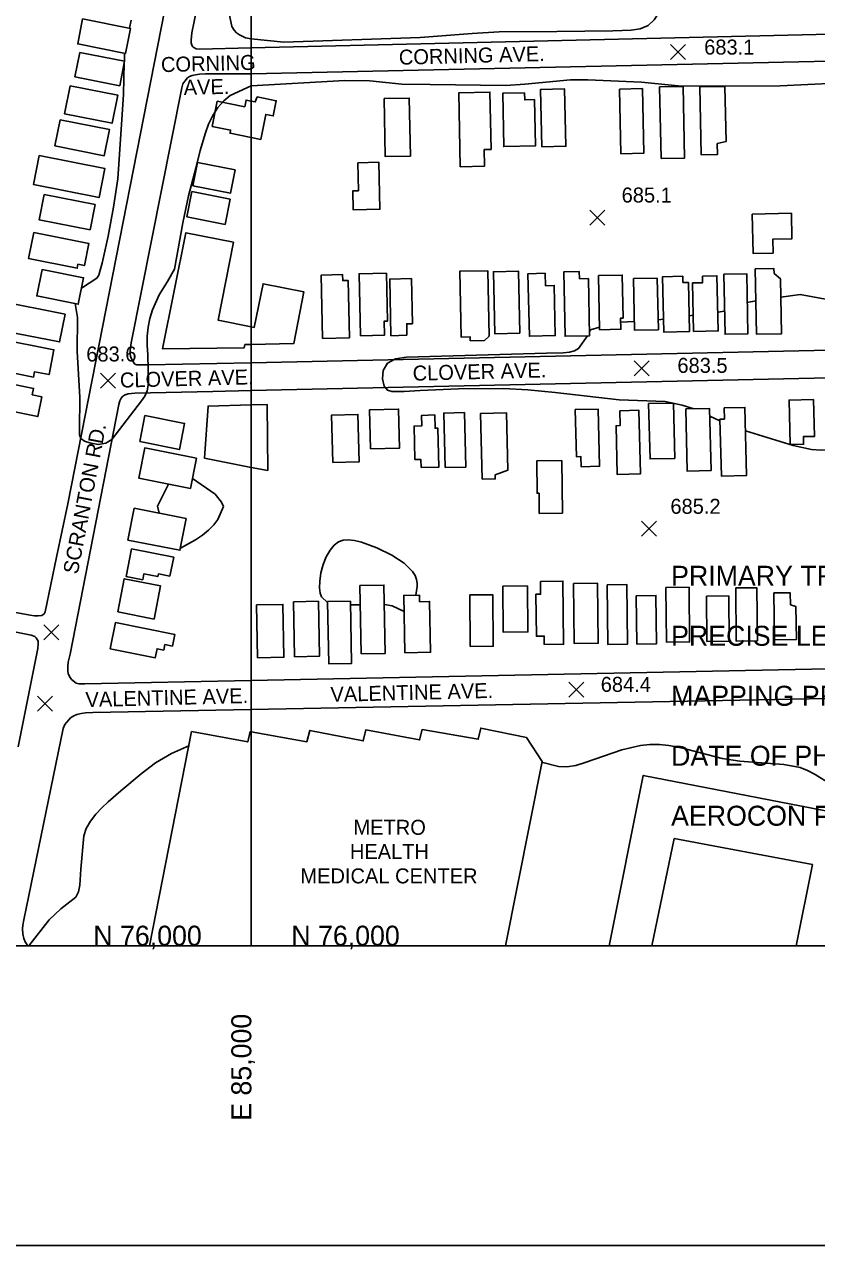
# Model space of a CAD drawing. Extents: x 79600 to 91800, y 75600 to 84400.
# Drawn here: x 84773 to 85566, y 75700 to 76922 of the extents above; entities that cross this region are included whole.
import ezdxf

# ---------------------------------------------------------------- set-up
doc = ezdxf.new("R2010")
doc.units = 0
for name, color, linetype in [('080-085$0$BLDG', 7, 'Continuous'), ('080-085$0$GRID', 7, 'Continuous'), ('080-085$0$INTER', 7, 'Continuous'), ('080-085$0$ROAD', 7, 'Continuous'), ('080-085$0$ROAD-NAME', 7, 'Continuous'), ('080-085$0$SPOTMARK', 7, 'Continuous'), ('080-085$0$SPOTS', 7, 'Continuous'), ('080-085$0$TI_BORDER', 7, 'Continuous'), ('080-085$0$TI_TITLE', 7, 'Continuous'), ('080-090$0$BLDG', 7, 'Continuous'), ('080-090$0$GRID', 7, 'Continuous'), ('080-090$0$INTER', 7, 'Continuous'), ('080-090$0$ROAD', 7, 'Continuous'), ('080-090$0$ROAD-NAME', 7, 'Continuous'), ('080-090$0$SPOTMARK', 7, 'Continuous'), ('080-090$0$SPOTS', 7, 'Continuous'), ('080-090$0$TI_BORDER', 7, 'Continuous')]:
    doc.layers.add(name, color=color, linetype=linetype)

# ---------------------------------------------------------------- blocks, each defined once
blk = doc.blocks.new('080-090$0$SPOTS')
at = {"layer": '080-090$0$SPOTMARK'}
for p, q in [((-0.5, -0.5), (0.5, 0.5)), ((-0.5, 0.5), (0.5, -0.5))]:
    blk.add_line(p, q, dxfattribs=at)
blk = doc.blocks.new('080-085$0$SPOTS')
at = {"layer": '080-085$0$SPOTMARK'}
for p, q in [((-0.5, -0.5), (0.5, 0.5)), ((-0.5, 0.5), (0.5, -0.5))]:
    blk.add_line(p, q, dxfattribs=at)

msp = doc.modelspace()

# ---------------------------------------------------------------- linework, layer by layer
at = {"layer": '080-085$0$BLDG'}
for points in [[(84831.2, 76927.1), (84826.3, 76902.1), (84874, 76892.6), (84879, 76917.6)], [(84828.3, 76893.6), (84823.5, 76869.2), (84868.3, 76860.3), (84873.2, 76884.7)], [(84818.7, 76860.2), (84813.2, 76832.1), (84860.7, 76822.7), (84866.3, 76850.8)], [(84808.7, 76826.2), (84803.5, 76800), (84852.8, 76790.2), (84858, 76816.5)], [(84787.9, 76790.3), (84782.2, 76761.4), (84847.7, 76748.4), (84853.5, 76777.3)], [(84946.2, 76783.6), (84983.8, 76776), (84979.1, 76752.6), (84941.5, 76760.2)], [(84792.6, 76751.5), (84787.6, 76726.2), (84838.7, 76716.1), (84843.7, 76741.4)], [(84940.5, 76754.3), (84978.8, 76746.6), (84973.8, 76721.5), (84935.5, 76729.2)], [(84782.4, 76713.3), (84777.2, 76687.3), (84825.8, 76677.7), (84826.6, 76681.6), (84833.1, 76680.3), (84837.5, 76702.3)], [(84790.6, 76676.5), (84785.3, 76649.9), (84826.9, 76641.7), (84832.2, 76668.2)], [(84746.5, 76645), (84743.4, 76629.5), (84757.3, 76626.7), (84754.9, 76614.5), (84808.2, 76603.9), (84813.7, 76631.7)], [(84745.2, 76607.4), (84741.5, 76588.8), (84734.9, 76590.2), (84732.6, 76578.6), (84782.1, 76568.8), (84783.1, 76574.1), (84797.6, 76571.3), (84802.5, 76596.1)], [(84780.9, 76550.9), (84782.2, 76557.5), (84743, 76565.4), (84740.2, 76551.7), (84729.2, 76553.9), (84726.6, 76541.3), (84786.4, 76529.3), (84790.3, 76549)], [(84888.4, 76504.2), (84893.6, 76530.2), (84933.3, 76522.4), (84928.1, 76496.3)], [(84945.1, 76487.6), (84893.4, 76497.9), (84887.4, 76467.7), (84939.1, 76457.4)], [(84934.9, 76427.2), (84882.9, 76437.5), (84876.6, 76405.8), (84928.6, 76395.5)], [(84918.6, 76369.6), (84907, 76371.9), (84906.4, 76369.3), (84892.6, 76372.1), (84891.4, 76366.1), (84874.7, 76369.4), (84880.2, 76396.9), (84922.4, 76388.5)], [(84866.3, 76333.9), (84872.8, 76367), (84909.3, 76359.8), (84902.7, 76326.7)], [(84921.1, 76299.7), (84913.5, 76301.2), (84912.4, 76295.7), (84905.7, 76297.1), (84903.9, 76288), (84858.8, 76297), (84864, 76323.2), (84923.4, 76311.4)]]:
    msp.add_lwpolyline(points, close=True, dxfattribs=at)
for points in [[(85000, 76808.4), (84978.7, 76812.7), (84979.3, 76815.8), (84960.9, 76819.5), (84965.9, 76844.7)], [(84965.9, 76844.7), (84993.5, 76839.2), (84994.8, 76845.9), (85000, 76844.8)], [(85000, 76601.4), (84993.6, 76601.3), (84992.9, 76598.1), (84911.3, 76596.9), (84934.6, 76713.2), (84982.3, 76703.6)], [(84982.3, 76703.6), (84966.7, 76625.8), (85000, 76619.1)], [(85000, 76541), (84956.8, 76539.8), (84953, 76487.8), (85000, 76478.5)], [(85000, 76213.9), (84999, 76214.1), (84996.4, 76203.8), (84940.3, 76214.2), (84898.2, 76000)]]:
    msp.add_lwpolyline(points, dxfattribs=at)
at = {"layer": '080-085$0$GRID'}
for p, q in [((85000, 80000), (85000, 76000)), ((85000, 76000), (80000, 76000))]:
    msp.add_line(p, q, dxfattribs=at)
at = {"layer": '080-085$0$INTER'}
for p, q in [((84879.7, 76925.7), (84878, 76917.8)), ((84873.1, 76892.8), (84873, 76884.8))]:
    msp.add_line(p, q, dxfattribs=at)
for points in [[(85000, 76907), (84994.2, 76908.2), (84988.3, 76911), (84985.3, 76913.2), (84982.7, 76915.9), (84980.6, 76919.6), (84977.9, 76932.5), (84974.5, 76968.3), (84973.5, 76986), (84974.5, 77004.8), (84977.5, 77023.9), (84981.9, 77041.5), (84990.1, 77066.8), (85000, 77090.7)], [(84872.9, 76883.5), (84872, 76851.5), (84867.9, 76786.7), (84866.3, 76767.2), (84862.1, 76738.6), (84856.7, 76709.8), (84850.7, 76682.6), (84848.9, 76675.8), (84847.3, 76670.9), (84845.4, 76667.6), (84830.1, 76657.7)], [(84823.9, 76642.3), (84826.2, 76628.4), (84825.9, 76594.5), (84828.5, 76548.8), (84828.1, 76516), (84828.2, 76511.1), (84829.5, 76507.5), (84833, 76504.8), (84839.3, 76502.6), (84847, 76501.5), (84854.4, 76502.6), (84860.3, 76506.5), (84890.1, 76545), (84893.4, 76549.6), (84895.8, 76555.1), (84897, 76562.8), (84896.5, 76591.2), (84895.9, 76600.6), (84895.9, 76609.7), (84896.8, 76618.8), (84898.6, 76627.5), (84901.2, 76635.9), (84907.9, 76651.1), (84916.1, 76664.3), (84923.3, 76676.9), (84931.5, 76723), (84937.3, 76750.2), (84944.4, 76777.7), (84948.9, 76795.3), (84954.1, 76813.1), (84957.3, 76821.9), (84961.4, 76830.4), (84966.5, 76838.3), (84972.5, 76845.1), (84979, 76850.6), (85000, 76860.2)], [(84917.2, 76461.8), (84906.2, 76439.8), (84907.7, 76432.6)], [(84972.2, 76439.3), (84970.1, 76443.7), (84963.8, 76451.6), (84941.1, 76467.4)], [(84929, 76397.6), (84944.2, 76406), (84951, 76410.5), (84957.2, 76415.6), (84962.4, 76421), (84966.4, 76426.2), (84972.2, 76439.3)], [(84938.3, 76200.1), (84920.1, 76192.1), (84904.1, 76182.8), (84889.7, 76171.9), (84869.3, 76155), (84856.7, 76144), (84850.5, 76138), (84844.5, 76131.5), (84839.1, 76124.5), (84834.9, 76117.2), (84832.3, 76109.9), (84829.3, 76076.7), (84828.3, 76060.4), (84827.1, 76053.9), (84824.6, 76048.6), (84809.5, 76037), (84797.9, 76025.7), (84777.3, 76000)]]:
    msp.add_lwpolyline(points, dxfattribs=at)
at = {"layer": '080-085$0$ROAD'}
for p, q in [((84998.9, 76872.3), (85000, 76872.3)), ((84961.6, 76554.4), (85000, 76555.2))]:
    msp.add_line(p, q, dxfattribs=at)
for points in [[(85000, 76898.1), (84948.3, 76896.9), (84944.7, 76897.2), (84942.4, 76898.4), (84941.4, 76899.2), (84940.5, 76900.9), (84939.8, 76903), (84939.9, 76905.9), (84940, 76909.5), (84940.4, 76913), (84994.1, 77174.3), (84995.6, 77179.1), (84997.7, 77182), (85000, 77184.1)], [(84689.6, 77082.2), (84919.5, 77085.7), (84922.4, 77085.8), (84925.3, 77085.5), (84928.1, 77085.1), (84930, 77084.1), (84931.5, 77083.2), (84934.4, 77080.5), (84936, 77078.5), (84937.6, 77075.6), (84938.3, 77072.8), (84938.5, 77068.1), (84938.3, 77064.6), (84937.5, 77059.2), (84816.4, 76442.1), (84805.1, 76388.5), (84793.6, 76333.9), (84792.6, 76331.9), (84790.3, 76330.3), (84786.7, 76330), (84783.1, 76330), (84778.8, 76330.6), (84673.2, 76350.1)], [(85000, 76583.2), (84896.8, 76581), (84891, 76580.9), (84885.6, 76581.2), (84884.5, 76581.5), (84883.2, 76582.2), (84882.1, 76583.6), (84879.7, 76587.6), (84879, 76589.6), (84878.7, 76592.1), (84878.7, 76595.7), (84879.9, 76603), (84930.4, 76858.1), (84931.4, 76862), (84933.4, 76864.9), (84936.1, 76868), (84938.3, 76869.4), (84940.8, 76870.6), (84944.2, 76871.2), (84948.3, 76871.8), (84954.3, 76872), (84998.9, 76872.3)], [(85000, 76265.2), (84833.3, 76261.8), (84827.5, 76261.8), (84824.9, 76262.6), (84820.2, 76266.2), (84818.6, 76268.4), (84816.8, 76271.8), (84816.3, 76275.1), (84816.3, 76279.4), (84816.7, 76283.7), (84818.7, 76291.5), (84867.4, 76541.2), (84868.5, 76545), (84869.7, 76547.6), (84871.6, 76549.8), (84873.9, 76551), (84876.9, 76552.1), (84880, 76552.3), (84883.5, 76552.7), (84961.6, 76554.4)], [(84641.7, 76338.4), (84779.6, 76310.5), (84783.3, 76309.4), (84784.7, 76308.1), (84786.6, 76304.5), (84786.8, 76301.8), (84786.5, 76297.4), (84766.6, 76199)], [(84776.2, 76000), (84775.3, 76001.4), (84774.2, 76003.2), (84772.5, 76007.2), (84771.4, 76011.8), (84771.2, 76016.7), (84771.3, 76020.6), (84772.3, 76025.8), (84811.6, 76217.1), (84813.4, 76221.1), (84815.1, 76223.4), (84817.4, 76225.9), (84819.2, 76227.8), (84822.3, 76229.8), (84825.3, 76231.2), (84829.7, 76232.2), (84834, 76232.9), (84841.6, 76233.1), (85000, 76236.2)]]:
    msp.add_lwpolyline(points, dxfattribs=at)
at = {"layer": '080-085$0$TI_BORDER'}
msp.add_lwpolyline([(79700, 80300), (86700, 80300), (86700, 75700), (79700, 75700)], close=True, dxfattribs=at)
at = {"layer": '080-090$0$BLDG'}
msp.add_line((85000, 76478.5), (85016.5, 76475.3), dxfattribs=at)
for points in [[(85000, 76844.8), (85003.9, 76844.1), (85005.9, 76849.1), (85025, 76845.2), (85022, 76830), (85014.5, 76831.5), (85009.5, 76806.5), (85000, 76808.4)], [(85000, 76619.1), (85003, 76618.5), (85011.7, 76662.2), (85052.7, 76653.9), (85042.4, 76602.3), (85000, 76601.4)], [(85016.5, 76475.3), (85015.8, 76541.5), (85000, 76541)], [(85254.2, 76000), (85291, 76184.4), (85275.3, 76208.2), (85229.6, 76217.6), (85227.1, 76206.5), (85170.9, 76216.2), (85168.4, 76205.8), (85114.5, 76215.9), (85112, 76204.9), (85058.7, 76215.3), (85055.4, 76204), (85000, 76213.9)], [(85358.1, 76000), (85392.2, 76170.4), (85612.5, 76127.6), (85587.5, 76000)], [(85400.8, 76000), (85423.2, 76107.1), (85561.4, 76081.1), (85545, 76000)]]:
    msp.add_lwpolyline(points, dxfattribs=at)
for points in [[(85240, 76796.5), (85233, 76796.4), (85233.4, 76779.8), (85209.1, 76779.2), (85207.5, 76853.1), (85238.8, 76853.8)], [(85273.3, 76853.1), (85273.5, 76846.1), (85283.3, 76846.3), (85284.2, 76800.1), (85252.6, 76799.4), (85251.5, 76852.7)], [(85290.6, 76799.2), (85314.8, 76799.7), (85313.5, 76857), (85289.4, 76856.5)], [(85368.4, 76856.9), (85369.7, 76792.2), (85392.6, 76792.7), (85391.3, 76857.4)], [(85409.9, 76787.3), (85433.4, 76787.8), (85431.9, 76859.5), (85408.4, 76859)], [(85466.2, 76802.5), (85466.4, 76791.3), (85450.1, 76791), (85448.7, 76859.1), (85473.9, 76859.6), (85475, 76804.3)], [(85132.8, 76847.3), (85134, 76789.3), (85159.2, 76789.8), (85158, 76847.9)], [(85106.5, 76783.2), (85107.1, 76755.2), (85101.6, 76755.1), (85102, 76736), (85128.6, 76736.6), (85127.6, 76783.7)], [(85522.2, 76692.9), (85521.9, 76706.8), (85540.8, 76707.2), (85540.3, 76732.6), (85501.1, 76731.7), (85502, 76692.5)], [(85071.3, 76607.5), (85070, 76670.8), (85091.3, 76671.3), (85091.4, 76665.3), (85096.9, 76665.4), (85098.2, 76608.1)], [(85109.1, 76610.1), (85107.8, 76672.1), (85135.1, 76672.6), (85136.1, 76624.7), (85132.9, 76624.6), (85133.2, 76610.6)], [(85155.7, 76610.6), (85155.5, 76622.1), (85161.1, 76622.2), (85160.1, 76667.4), (85138.5, 76666.9), (85139.7, 76610.2)], [(85233.4, 76605.5), (85219.1, 76605.2), (85219, 76609), (85209.9, 76608.8), (85208.5, 76674.6), (85236.6, 76675.2), (85238, 76609.8)], [(85268.7, 76612.7), (85243.6, 76612.2), (85242.3, 76674.1), (85267.4, 76674.6)], [(85294.2, 76660.2), (85293.9, 76672.6), (85276.8, 76672.2), (85278.2, 76609.7), (85304.1, 76610.3), (85303, 76660.4)], [(85328.2, 76667.1), (85328.1, 76674.3), (85312.6, 76674), (85314, 76609.6), (85338.4, 76610.1), (85337.2, 76667.3)], [(85347.4, 76670.4), (85348.5, 76616.2), (85369.7, 76616.6), (85369.4, 76627.8), (85372, 76627.8), (85371.1, 76670.9)], [(85406.2, 76667.8), (85382.4, 76667.3), (85383.5, 76615.7), (85407.3, 76616.2)], [(85431.8, 76663.4), (85431.7, 76669.6), (85411.4, 76669.2), (85412.6, 76613.8), (85438.3, 76614.3), (85437.3, 76663.5)], [(85451.3, 76669.9), (85451.5, 76663.2), (85441.4, 76663), (85442.4, 76614.4), (85467.1, 76614.9), (85465.9, 76670.2)], [(85472.7, 76671.8), (85474, 76611.6), (85496.9, 76612.1), (85495.6, 76672.2)], [(85523, 76672.3), (85522.9, 76677.4), (85504.1, 76677), (85505.5, 76611.7), (85530.5, 76612.2), (85529.3, 76667.1)], [(85562.6, 76546.3), (85563.5, 76509.5), (85552.3, 76509.2), (85552.5, 76501.6), (85539.2, 76501.2), (85538.1, 76545.7)], [(85081.5, 76483.3), (85080.3, 76530.7), (85106.7, 76531.4), (85107.9, 76484)], [(85119.4, 76496.9), (85118.4, 76536.1), (85147.3, 76536.8), (85148.2, 76497.6)], [(85193.8, 76478.3), (85192.5, 76532.8), (85213.2, 76533.3), (85214.5, 76478.8)], [(85243.9, 76470.9), (85244, 76467), (85231, 76466.7), (85229.3, 76532.4), (85255.3, 76533.1), (85256.7, 76475.8)], [(85324, 76536.2), (85325.2, 76489.1), (85329.8, 76489.2), (85330, 76479.1), (85348.4, 76479.6), (85347, 76536.7)], [(85368.6, 76535.1), (85369, 76520.2), (85364.9, 76520.1), (85366, 76471.5), (85389.4, 76472.1), (85387.8, 76535.6)], [(85397.5, 76542.2), (85398.9, 76486.9), (85423.7, 76487.5), (85422.3, 76542.8)], [(85434.6, 76536.9), (85436.1, 76474.6), (85460, 76475.2), (85458.4, 76537.5)], [(85473, 76538), (85473.3, 76526.7), (85468.9, 76526.6), (85470.3, 76469.8), (85495.5, 76470.4), (85493.8, 76538.5)], [(85169.8, 76478.3), (85169.6, 76486.4), (85163.7, 76486.3), (85162.9, 76519.7), (85170.6, 76519.9), (85170.3, 76530.5), (85183.6, 76530.9), (85183.9, 76517.6), (85186.7, 76517.6), (85187.7, 76478.8)], [(85288.1, 76432.4), (85287.9, 76452.5), (85285.9, 76452.5), (85285.5, 76485), (85310.6, 76485.3), (85311.2, 76432.7)], [(85108.6, 76360.3), (85110, 76292), (85134, 76292.4), (85132.7, 76360.7)], [(85289.3, 76364.4), (85289.4, 76351.6), (85284.8, 76351.5), (85285.3, 76309.6), (85293, 76309.7), (85293.1, 76301.2), (85312.4, 76301.5), (85311.7, 76364.7)], [(85322.2, 76362.3), (85322.9, 76302.4), (85347.1, 76302.6), (85346.4, 76362.6)], [(85355.9, 76361.1), (85356.6, 76301.4), (85376.3, 76301.6), (85375.6, 76361.3)], [(85168.3, 76344.1), (85168.2, 76350.7), (85152.5, 76350.4), (85153.6, 76293), (85179.3, 76293.5), (85178.3, 76344.3)], [(85218.5, 76350.8), (85219.1, 76299.3), (85242.1, 76299.6), (85241.5, 76351.1)], [(85251.6, 76359.5), (85252.1, 76313.5), (85276.8, 76313.8), (85276.3, 76359.8)], [(85385.2, 76350.1), (85385.8, 76301.7), (85405.3, 76301.9), (85404.8, 76350.3)], [(85414.8, 76358.2), (85415.5, 76303.6), (85438.5, 76303.9), (85437.9, 76358.5)], [(85455.4, 76349.6), (85455.9, 76304.3), (85478.1, 76304.6), (85477.6, 76349.9)], [(85484.6, 76357.9), (85485.2, 76304.6), (85506.3, 76304.8), (85505.7, 76358.1)], [(85539.3, 76341), (85539.1, 76353), (85522.8, 76352.8), (85523.3, 76306), (85545.3, 76306.2), (85544.9, 76339.2)], [(85005.3, 76340.9), (85006.3, 76288.1), (85032.7, 76288.6), (85031.7, 76341.4)], [(85042.2, 76344.1), (85043.3, 76289), (85068.1, 76289.5), (85067.1, 76344.5)], [(85076.3, 76344.2), (85077.5, 76282), (85100.3, 76282.4), (85099.1, 76344.6)]]:
    msp.add_lwpolyline(points, close=True, dxfattribs=at)
at = {"layer": '080-090$0$GRID'}
for p in [(85000, 80000), (90000, 76000)]:
    msp.add_line(p, (85000, 76000), dxfattribs=at)
at = {"layer": '080-090$0$INTER'}
for p, q in [((85496.2, 76643.4), (85504.8, 76645.1)), ((85438, 76630.1), (85442.1, 76630.8)), ((85466.7, 76633.7), (85473.5, 76634.7)), ((85369.5, 76623.8), (85383.3, 76624.4)), ((85407.1, 76626.2), (85412.3, 76626.6)), ((85468.9, 76525.1), (85458.6, 76529.7)), ((85099.1, 76340.9), (85109, 76340.8))]:
    msp.add_line(p, q, dxfattribs=at)
for points in [[(85000, 76907), (85032.4, 76903.9), (85169.1, 76908.6), (85221.1, 76912.5), (85248.1, 76914.1), (85305.8, 76914.4), (85361.8, 76915.2), (85370.9, 76915.4), (85380.2, 76915.8), (85389.2, 76917.2), (85397, 76920.5), (85403.2, 76926.1), (85420.1, 76952.6)], [(85651.5, 76862.4), (85627.5, 76861.5), (85584.6, 76862.7), (85529.1, 76860.2), (85453.8, 76859.8), (85427.1, 76860.3), (85390.3, 76863.7), (85336.8, 76866.2), (85319.2, 76866.3), (85273.6, 76861.7), (85254.6, 76860.5), (85179.1, 76861.4), (85150.5, 76861.7), (85118.6, 76865.3), (85093.7, 76865.5), (85000, 76860.2)], [(85529.7, 76648.7), (85549.1, 76651.3), (85574.6, 76646.7)], [(85338.3, 76614.1), (85339.3, 76615.9), (85348.5, 76618.8)], [(85442.8, 76537.1), (85431.1, 76540.6), (85414.1, 76544.3), (85367.9, 76546.1), (85304.1, 76553.5), (85276.5, 76556.1), (85252.3, 76557.3), (85207.3, 76556.9), (85168.9, 76555.2), (85152.8, 76554.2), (85140.6, 76554.2), (85136.1, 76555.8), (85132.9, 76559.8), (85131.2, 76567), (85131.9, 76575.3), (85136.1, 76582.6), (85144.4, 76586.9), (85155.4, 76588.8), (85295.2, 76592.8), (85312.1, 76593), (85318.4, 76593.7), (85323.4, 76595), (85327.4, 76597.3), (85336.2, 76610.1)], [(85647.2, 76514.8), (85624.4, 76507.3), (85607.1, 76502.4), (85588.7, 76497.8), (85579.4, 76496.2), (85570, 76495.6), (85560.6, 76496.3), (85542.2, 76500.4), (85494.4, 76515)], [(85164.6, 76350.7), (85166, 76359.4), (85166, 76362.7), (85165.3, 76366.4), (85163.8, 76370.3), (85161.2, 76374.4), (85152.8, 76382.7), (85140.5, 76390.8), (85125.7, 76398.1), (85110.4, 76403.5), (85103.3, 76405.2), (85097, 76405.9), (85091.8, 76405.6), (85087.2, 76404), (85083, 76400.7), (85078.9, 76395.6), (85075, 76389), (85071.9, 76381.3), (85069.7, 76372.9), (85068.5, 76364.8), (85068.3, 76357.8), (85068.9, 76352.6), (85070.1, 76349), (85076.3, 76343.3)], [(85133.1, 76341.4), (85140.8, 76339.8), (85152.8, 76334.3)], [(85594.1, 76152.6), (85564, 76171.1), (85556.5, 76175.4), (85549, 76178.3), (85532.9, 76181.2), (85506.2, 76183.3), (85488.9, 76184.6), (85471.1, 76187.3), (85435.5, 76196.6), (85426.9, 76198.7), (85417.7, 76200.2), (85408.3, 76201.1), (85398.8, 76201.1), (85389.4, 76200.1), (85370.8, 76195.9), (85333.9, 76183.1), (85324.7, 76180.4), (85315.8, 76179), (85307.3, 76179.4), (85290.4, 76183.6)]]:
    msp.add_lwpolyline(points, dxfattribs=at)
at = {"layer": '080-090$0$ROAD'}
for p, q in [((85860.3, 76918.4), (85000, 76898.1)), ((85000, 76872.3), (85854.6, 76890.9)), ((85777.9, 76599.9), (85000, 76583.2)), ((85000, 76555.2), (85765.8, 76572.2)), ((85689.7, 76279.4), (85000, 76265.2)), ((85000, 76236.2), (85855.8, 76252.6))]:
    msp.add_line(p, q, dxfattribs=at)
at = {"layer": '080-090$0$TI_BORDER'}
msp.add_lwpolyline([(84700, 80300), (91700, 80300), (91700, 75700), (84700, 75700)], close=True, dxfattribs=at)

# ---------------------------------------------------------------- block references
at = {"layer": '080-085$0$SPOTMARK', "xscale": 15, "yscale": 15}
for p in [(84856.5, 76565.1), (84799.9, 76313.4), (84793.6, 76242)]:
    msp.add_blockref('080-085$0$SPOTS', p, dxfattribs=at)
at = {"layer": '080-090$0$SPOTMARK', "xscale": 15, "yscale": 15}
for p in [(85426.9, 76894.1), (85346.1, 76728.4), (85390.7, 76577.4), (85398, 76417), (85325.1, 76256.2)]:
    msp.add_blockref('080-090$0$SPOTS', p, dxfattribs=at)

# ---------------------------------------------------------------- texts
at = {"layer": '080-085$0$GRID'}
msp.add_text('N 76,000', height=20, dxfattribs=at).set_placement((85040, 76000))
msp.add_text('E 85,000', height=20, rotation=90, dxfattribs=at).set_placement((85000, 75824.8))
at = {"layer": '080-085$0$ROAD-NAME'}
for s, rotation, p in [('CORNING', 1.4497, (84909.8, 76873.8)), ('AVE.', 1.4497, (84932.5, 76851)), ('CLOVER AVE.', 1.4497, (84868.7, 76558.2)), ('SCRANTON RD.', 79.2031, (84826.3, 76370.9)), ('VALENTINE AVE.', 1.4497, (84834.3, 76238.6))]:
    msp.add_text(s, height=15, rotation=rotation, dxfattribs=at).set_placement(p)
at = {"layer": '080-085$0$SPOTS'}
msp.add_text('683.6', height=15, dxfattribs=at).set_placement((84834.9, 76584.4))
at = {"layer": '080-085$0$TI_TITLE'}
for s, p in [('PRIMARY TRAVERSE : CLEVELAND REGIONAL GEODETIC SURVEY', (85420, 76360)), ('PRECISE LEVELS : CLEVELAND REGIONAL GEODETIC SURVEY', (85420, 76300)), ('MAPPING PREPARED BY PHOTOGRAMMETRIC METHODS', (85420, 76240)), ('DATE OF PHOTOGRAPHY : APRIL 1993', (85420, 76180)), ('AEROCON PHOTOGRAMMETRIC SERVICES INC., WILLOUGHBY, OHIO', (85420, 76120))]:
    msp.add_text(s, height=20, dxfattribs=at).set_placement(p)
at = {"layer": '080-090$0$GRID'}
msp.add_text('N 76,000', height=20, dxfattribs=at).set_placement((84841.9, 76000))
msp.add_text('E 85,000', height=20, rotation=90, dxfattribs=at).set_placement((85000, 75824.8))
at = {"layer": '080-090$0$ROAD-NAME'}
for s, p in [('CORNING AVE.', (85147.8, 76881.2)), ('CLOVER AVE.', (85161.6, 76565.1)), ('VALENTINE AVE.', (85079.4, 76243.8))]:
    msp.add_text(s, height=15, rotation=1.4497, dxfattribs=at).set_placement(p)
for s, p in [('METRO', (85102.2, 76110.9)), ('HEALTH', (85098.6, 76086.6)), ('MEDICAL CENTER', (85049.1, 76062.3))]:
    msp.add_text(s, height=15, dxfattribs=at).set_placement(p)
at = {"layer": '080-090$0$SPOTS'}
for s, p in [('683.1', (85453.1, 76891.4)), ('685.1', (85370.5, 76743.4)), ('683.5', (85426.3, 76573)), ('685.2', (85419.3, 76432)), ('684.4', (85349.6, 76253.9))]:
    msp.add_text(s, height=15, dxfattribs=at).set_placement(p)

doc.saveas('drawing.dxf')
